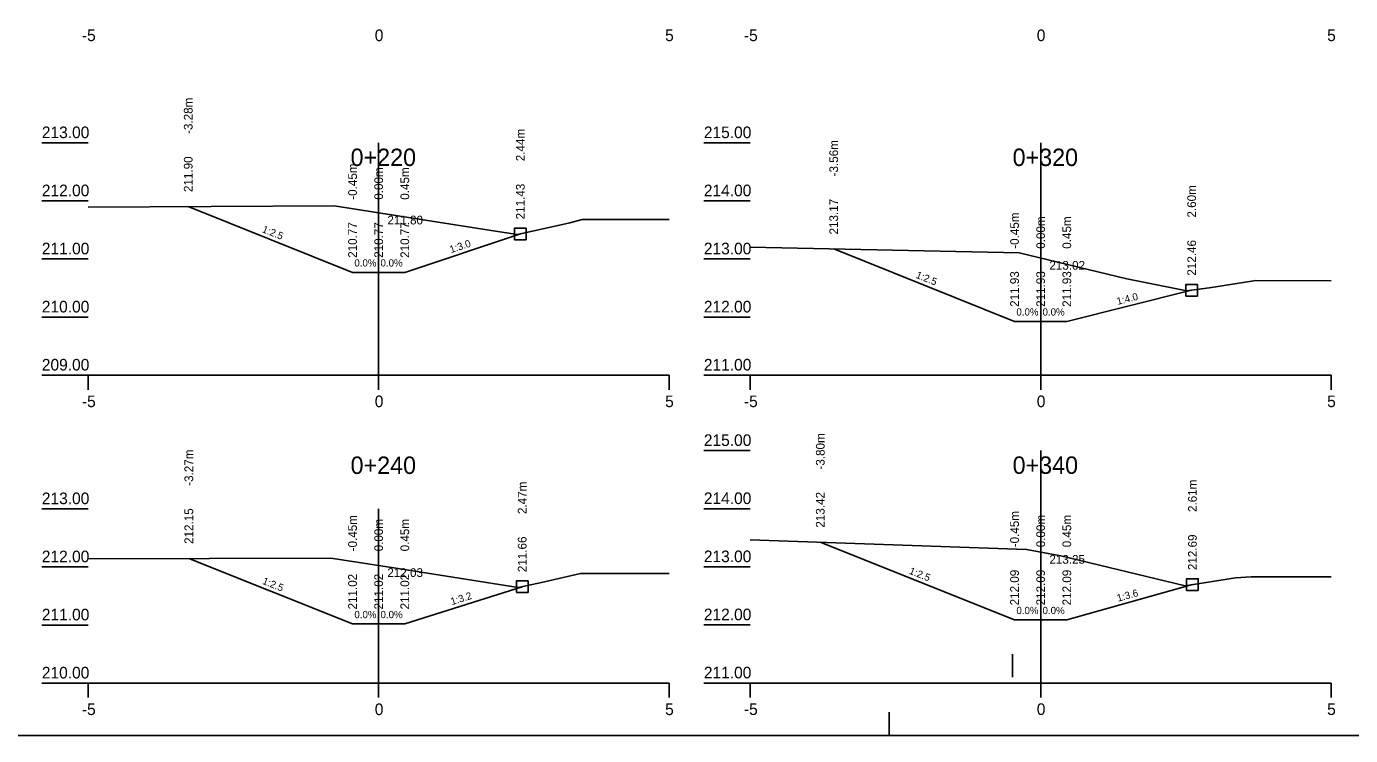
# Model space of a CAD drawing. Extents: x -577315 to -577212, y -1159820 to -1159790.
# Drawn here: x -577290.21 to -577267.41, y -1159820.05 to -1159807.85 of the extents above; entities that cross this region are included whole.
import ezdxf

# ---------------------------------------------------------------- set-up
doc = ezdxf.new("R2010")
doc.units = 0
for name, color, linetype in [('16', 7, 'Continuous'), ('21', 7, 'Continuous'), ('28', 7, 'Continuous'), ('59', 7, 'Continuous'), ('Body pricny rez', 7, 'Continuous'), ('Hranice_pozemku', 7, 'Continuous'), ('Popis pricneho profilu', 7, 'Continuous'), ('Rámy', 7, 'Continuous')]:
    doc.layers.add(name, color=color, linetype=linetype)

msp = doc.modelspace()

# ---------------------------------------------------------------- linework, layer by layer
for points in [[(-577289.143, -1159810.957), (-577284.907, -1159810.933), (-577282.13, -1159811.37), (-577281.752, -1159811.428), (-577280.851, -1159811.225), (-577280.64, -1159811.169), (-577279.143, -1159811.167)], [(-577284.593, -1159812.079), (-577287.422, -1159810.947)], [(-577283.693, -1159812.079), (-577281.703, -1159811.417)], [(-577277.743, -1159811.647), (-577273.116, -1159811.744), (-577271.258, -1159812.19), (-577270.226, -1159812.396), (-577269.801, -1159812.341), (-577269.037, -1159812.22), (-577267.743, -1159812.223)], [(-577273.193, -1159812.923), (-577276.307, -1159811.677)], [(-577284.593, -1159812.079), (-577284.143, -1159812.079), (-577283.693, -1159812.079)], [(-577272.293, -1159812.923), (-577270.143, -1159812.386)], [(-577273.193, -1159812.923), (-577272.743, -1159812.923), (-577272.293, -1159812.923)], [(-577277.743, -1159816.681), (-577272.986, -1159816.848), (-577272.393, -1159816.96), (-577270.253, -1159817.473), (-577269.386, -1159817.337), (-577269.119, -1159817.32), (-577267.743, -1159817.32)], [(-577273.193, -1159818.061), (-577276.538, -1159816.723)], [(-577289.143, -1159817.007), (-577284.964, -1159816.998), (-577283.882, -1159817.162), (-577281.738, -1159817.504), (-577281.34, -1159817.416), (-577280.666, -1159817.264), (-577279.143, -1159817.265)], [(-577284.593, -1159818.131), (-577287.412, -1159817.003)], [(-577283.693, -1159818.131), (-577281.671, -1159817.489)], [(-577272.293, -1159818.061), (-577270.13, -1159817.454)], [(-577284.593, -1159818.131), (-577284.143, -1159818.131), (-577283.693, -1159818.131)], [(-577273.193, -1159818.061), (-577272.743, -1159818.061), (-577272.293, -1159818.061)]]:
    msp.add_lwpolyline(points)
at = {"layer": '16'}
for p, q in [((-577289.143, -1159813.849), (-577279.143, -1159813.849)), ((-577277.743, -1159813.849), (-577267.743, -1159813.849)), ((-577289.143, -1159819.149), (-577279.143, -1159819.149)), ((-577277.743, -1159819.147), (-577267.743, -1159819.147))]:
    msp.add_line(p, q, dxfattribs=at)
at = {"layer": '21'}
for p, q in [((-577289.943, -1159809.849), (-577289.143, -1159809.849)), ((-577278.543, -1159809.849), (-577277.743, -1159809.849)), ((-577289.943, -1159810.849), (-577289.143, -1159810.849)), ((-577278.543, -1159810.849), (-577277.743, -1159810.849)), ((-577289.943, -1159811.849), (-577289.143, -1159811.849)), ((-577278.543, -1159811.849), (-577277.743, -1159811.849)), ((-577289.943, -1159812.849), (-577289.143, -1159812.849)), ((-577278.543, -1159812.849), (-577277.743, -1159812.849)), ((-577289.943, -1159813.849), (-577289.143, -1159813.849)), ((-577278.543, -1159813.849), (-577277.743, -1159813.849)), ((-577278.543, -1159815.147), (-577277.743, -1159815.147)), ((-577289.943, -1159816.149), (-577289.143, -1159816.149)), ((-577278.543, -1159816.147), (-577277.743, -1159816.147)), ((-577289.943, -1159817.149), (-577289.143, -1159817.149)), ((-577278.543, -1159817.147), (-577277.743, -1159817.147)), ((-577289.943, -1159818.149), (-577289.143, -1159818.149)), ((-577278.543, -1159818.147), (-577277.743, -1159818.147)), ((-577289.943, -1159819.149), (-577289.143, -1159819.149)), ((-577278.543, -1159819.147), (-577277.743, -1159819.147))]:
    msp.add_line(p, q, dxfattribs=at)
at = {"layer": '28'}
for p, q in [((-577284.143, -1159809.849), (-577284.143, -1159813.849)), ((-577272.743, -1159809.849), (-577272.743, -1159813.849)), ((-577272.743, -1159815.147), (-577272.743, -1159819.147)), ((-577284.143, -1159816.149), (-577284.143, -1159819.149))]:
    msp.add_line(p, q, dxfattribs=at)
at = {"layer": '59'}
for p, q in [((-577289.143, -1159814.099), (-577289.143, -1159813.849)), ((-577284.143, -1159814.099), (-577284.143, -1159813.849)), ((-577279.143, -1159814.099), (-577279.143, -1159813.849)), ((-577277.743, -1159814.099), (-577277.743, -1159813.849)), ((-577272.743, -1159814.099), (-577272.743, -1159813.849)), ((-577267.743, -1159814.099), (-577267.743, -1159813.849)), ((-577289.143, -1159819.399), (-577289.143, -1159819.149)), ((-577284.143, -1159819.399), (-577284.143, -1159819.149)), ((-577279.143, -1159819.399), (-577279.143, -1159819.149)), ((-577277.743, -1159819.397), (-577277.743, -1159819.147)), ((-577272.743, -1159819.397), (-577272.743, -1159819.147)), ((-577267.743, -1159819.397), (-577267.743, -1159819.147))]:
    msp.add_line(p, q, dxfattribs=at)
at = {"layer": 'Hranice_pozemku'}
for points in [[(-577281.803, -1159811.517), (-577281.603, -1159811.517), (-577281.603, -1159811.317), (-577281.803, -1159811.317)], [(-577270.243, -1159812.486), (-577270.043, -1159812.486), (-577270.043, -1159812.286), (-577270.243, -1159812.286)], [(-577281.771, -1159817.589), (-577281.571, -1159817.589), (-577281.571, -1159817.389), (-577281.771, -1159817.389)], [(-577270.23, -1159817.554), (-577270.03, -1159817.554), (-577270.03, -1159817.354), (-577270.23, -1159817.354)]]:
    msp.add_lwpolyline(points, close=True, dxfattribs=at)
at = {"layer": 'Rámy'}
for p, q in [((-577273.23, -1159819.049), (-577273.23, -1159818.649)), ((-577275.353, -1159820.051), (-577275.353, -1159819.651))]:
    msp.add_line(p, q, dxfattribs=at)
msp.add_lwpolyline([(-577315.23, -1159790.351), (-577212.353, -1159790.351), (-577212.353, -1159820.051), (-577315.23, -1159820.051)], close=True, dxfattribs=at)

# ---------------------------------------------------------------- texts
for s, height, p in [('0+220', 0.3, (-577284.626, -1159810.249)), ('0+320', 0.3, (-577273.226, -1159810.249)), ('+', 0.001, (-577284.143, -1159812.079)), ('+', 0.001, (-577272.743, -1159812.923)), ('0+240', 0.3, (-577284.626, -1159815.549)), ('0+340', 0.3, (-577273.226, -1159815.547)), ('+', 0.001, (-577284.143, -1159818.131)), ('+', 0.001, (-577272.743, -1159818.062))]:
    msp.add_text(s, height=height).set_placement(p)
for s, rotation, p in [('1:2.5', 338.1986, (-577286.161, -1159811.384)), ('1:3.0', 18.3942, (-577282.897, -1159811.749)), ('1:2.5', 338.1986, (-577274.903, -1159812.171)), ('1:4.0', 14.0303, (-577271.417, -1159812.64)), ('1:2.5', 338.1986, (-577275.019, -1159817.263)), ('1:2.5', 338.1986, (-577286.156, -1159817.438)), ('1:3.6', 15.6843, (-577271.411, -1159817.749)), ('1:3.2', 17.6005, (-577282.881, -1159817.808))]:
    msp.add_text(s, height=0.125, rotation=rotation).set_placement(p)
at = {"layer": '16'}
for p in [(-577284.561, -1159811.979), (-577284.111, -1159811.979), (-577273.161, -1159812.823), (-577272.711, -1159812.823), (-577284.561, -1159818.031), (-577284.111, -1159818.031), (-577273.161, -1159817.961), (-577272.711, -1159817.961)]:
    msp.add_text('0.0%', height=0.125, rotation=360, dxfattribs=at).set_placement(p)
at = {"layer": '21'}
for s, p in [('-5', (-577289.253, -1159808.099)), ('0', (-577284.21, -1159808.099)), ('5', (-577279.21, -1159808.099)), ('-5', (-577277.853, -1159808.099)), ('0', (-577272.81, -1159808.099)), ('5', (-577267.81, -1159808.099)), ('213.00', (-577289.943, -1159809.769)), ('215.00', (-577278.543, -1159809.769)), ('212.00', (-577289.943, -1159810.769)), ('214.00', (-577278.543, -1159810.769)), ('211.00', (-577289.943, -1159811.769)), ('213.00', (-577278.543, -1159811.769)), ('210.00', (-577289.943, -1159812.769)), ('212.00', (-577278.543, -1159812.769)), ('209.00', (-577289.943, -1159813.769)), ('211.00', (-577278.543, -1159813.769)), ('-5', (-577289.253, -1159814.399)), ('0', (-577284.21, -1159814.399)), ('5', (-577279.21, -1159814.399)), ('-5', (-577277.853, -1159814.399)), ('0', (-577272.81, -1159814.399)), ('5', (-577267.81, -1159814.399)), ('215.00', (-577278.543, -1159815.067)), ('213.00', (-577289.943, -1159816.069)), ('214.00', (-577278.543, -1159816.067)), ('212.00', (-577289.943, -1159817.069)), ('213.00', (-577278.543, -1159817.067)), ('211.00', (-577289.943, -1159818.069)), ('212.00', (-577278.543, -1159818.067)), ('210.00', (-577289.943, -1159819.069)), ('211.00', (-577278.543, -1159819.067)), ('-5', (-577289.253, -1159819.699)), ('0', (-577284.21, -1159819.699)), ('5', (-577279.21, -1159819.699)), ('-5', (-577277.853, -1159819.697)), ('0', (-577272.81, -1159819.697)), ('5', (-577267.81, -1159819.697))]:
    msp.add_text(s, height=0.2, dxfattribs=at).set_placement(p)
at = {"layer": '59'}
for s, p in [('211.80', (-577283.993, -1159811.254)), ('213.02', (-577272.593, -1159812.033)), ('213.25', (-577272.593, -1159817.094)), ('212.03', (-577283.993, -1159817.322))]:
    msp.add_text(s, height=0.15, dxfattribs=at).set_placement(p)
at = {"layer": 'Body pricny rez'}
for p in [(-577287.423, -1159810.948), (-577281.703, -1159811.418), (-577276.307, -1159811.678), (-577284.593, -1159812.079), (-577283.693, -1159812.079), (-577270.144, -1159812.386), (-577273.193, -1159812.923), (-577272.293, -1159812.923), (-577276.538, -1159816.724), (-577287.412, -1159817.004), (-577281.671, -1159817.49), (-577270.131, -1159817.455), (-577284.593, -1159818.131), (-577283.693, -1159818.131), (-577273.193, -1159818.062), (-577272.293, -1159818.062)]:
    msp.add_text('+', height=0.001, dxfattribs=at).set_placement(p)
at = {"layer": 'Popis pricneho profilu'}
for s, p in [('-3.28m', (-577287.347, -1159809.697)), ('2.44m', (-577281.628, -1159810.167)), ('2.44m', (-577281.628, -1159810.167)), ('2.44m', (-577281.628, -1159810.167)), ('-3.56m', (-577276.232, -1159810.427)), ('211.90', (-577287.347, -1159810.697)), ('-0.45m', (-577284.518, -1159810.829)), ('0.00m', (-577284.068, -1159810.829)), ('0.45m', (-577283.618, -1159810.829)), ('211.43', (-577281.628, -1159811.167)), ('2.60m', (-577270.068, -1159811.136)), ('2.60m', (-577270.068, -1159811.136)), ('2.60m', (-577270.068, -1159811.136)), ('213.17', (-577276.232, -1159811.427)), ('-0.45m', (-577273.118, -1159811.673)), ('0.00m', (-577272.668, -1159811.673)), ('0.45m', (-577272.218, -1159811.673)), ('210.77', (-577284.518, -1159811.829)), ('210.77', (-577284.068, -1159811.829)), ('210.77', (-577283.618, -1159811.829)), ('212.46', (-577270.068, -1159812.136)), ('211.93', (-577273.118, -1159812.673)), ('211.93', (-577272.668, -1159812.673)), ('211.93', (-577272.218, -1159812.673)), ('-3.80m', (-577276.463, -1159815.473)), ('-3.27m', (-577287.337, -1159815.753)), ('2.47m', (-577281.596, -1159816.239)), ('2.47m', (-577281.596, -1159816.239)), ('2.47m', (-577281.596, -1159816.239)), ('2.61m', (-577270.055, -1159816.204)), ('2.61m', (-577270.055, -1159816.204)), ('2.61m', (-577270.055, -1159816.204)), ('213.42', (-577276.463, -1159816.473)), ('212.15', (-577287.337, -1159816.753)), ('-0.45m', (-577284.518, -1159816.881)), ('0.00m', (-577284.068, -1159816.881)), ('0.45m', (-577283.618, -1159816.881)), ('-0.45m', (-577273.118, -1159816.811)), ('0.00m', (-577272.668, -1159816.811)), ('0.45m', (-577272.218, -1159816.811)), ('212.69', (-577270.055, -1159817.204)), ('211.66', (-577281.596, -1159817.239)), ('211.02', (-577284.518, -1159817.881)), ('211.02', (-577284.068, -1159817.881)), ('211.02', (-577283.618, -1159817.881)), ('212.09', (-577273.118, -1159817.811)), ('212.09', (-577272.668, -1159817.811)), ('212.09', (-577272.218, -1159817.811))]:
    msp.add_text(s, height=0.15, rotation=90, dxfattribs=at).set_placement(p)

doc.saveas('drawing.dxf')
